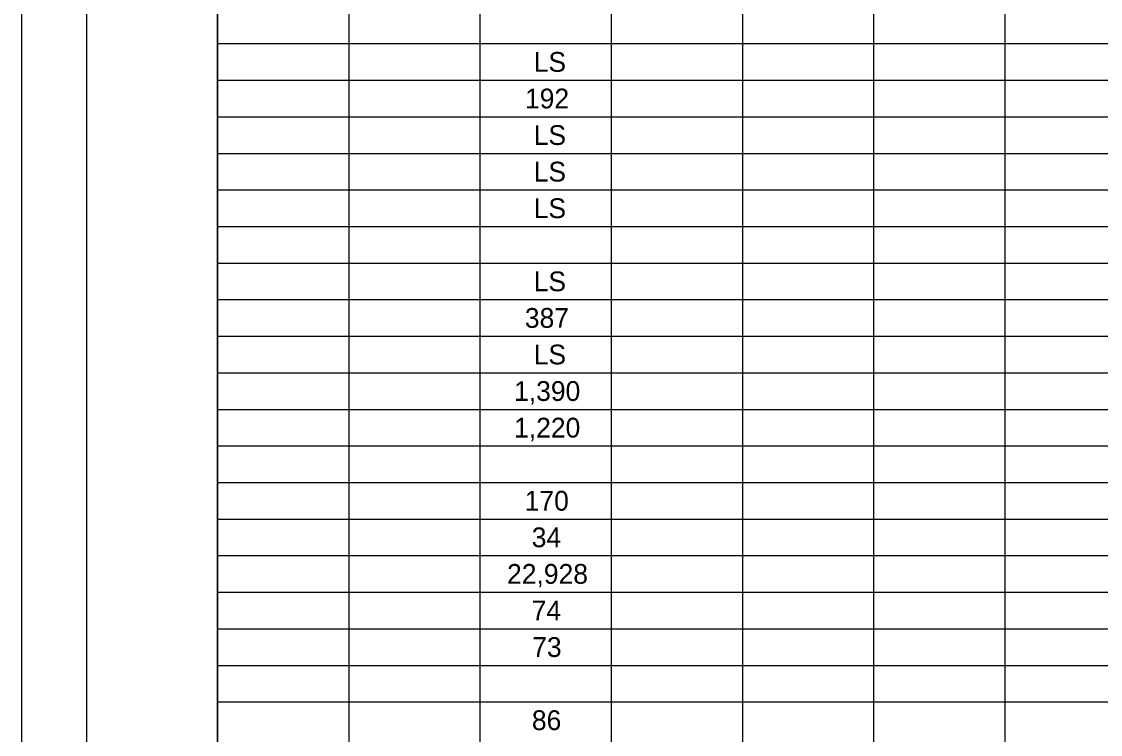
# Model space of a CAD drawing. Extents: x 0 to 34, y 0 to 22.
# Drawn here: x 0 to 8.26, y 10.89 to 16.35 of the extents above; entities that cross this region are included whole.
import ezdxf

# ---------------------------------------------------------------- set-up
doc = ezdxf.new("R2010")
doc.units = 0
for name, color, linetype in [('SH_Border', 7, 'Continuous'), ('SH_Cut_Line', 7, 'Continuous'), ('SH_Text', 7, 'Continuous')]:
    doc.layers.add(name, color=color, linetype=linetype)

msp = doc.modelspace()

# ---------------------------------------------------------------- linework, layer by layer
at = {"layer": 'SH_Border'}
for points in [[(0.5, 21.5), (1.5, 21.5), (1.5, 0.5), (0.5, 0.5)], [(1.5, 21.5), (33.5, 21.5), (33.5, 0.5), (1.5, 0.5)]]:
    msp.add_lwpolyline(points, close=True, dxfattribs=at)
at = {"layer": 'SH_Cut_Line'}
msp.add_lwpolyline([(0, 0), (34, 0), (34, 22), (0, 22)], close=True, dxfattribs=at)
at = {"layer": 'SH_Text'}
for p, q in [((1.5, 21.5), (1.5, 0.5)), ((2.5046, 20.94), (2.5046, 0.5)), ((3.5092, 20.94), (3.5092, 0.5)), ((4.5138, 20.94), (4.5138, 0.5)), ((5.5184, 20.94), (5.5184, 0.5)), ((6.5229, 20.94), (6.5229, 0.5)), ((7.5275, 20.94), (7.5275, 0.5)), ((1.5, 16.18), (32, 16.18)), ((1.5, 15.9), (32, 15.9)), ((1.5, 15.62), (32, 15.62)), ((1.5, 15.34), (32, 15.34)), ((1.5, 15.06), (32, 15.06)), ((1.5, 14.78), (32, 14.78)), ((1.5, 14.5), (32, 14.5)), ((1.5, 14.22), (32, 14.22)), ((1.5, 13.94), (32, 13.94)), ((1.5, 13.66), (32, 13.66)), ((1.5, 13.38), (32, 13.38)), ((1.5, 13.1), (32, 13.1)), ((1.5, 12.82), (32, 12.82)), ((1.5, 12.54), (32, 12.54)), ((1.5, 12.26), (32, 12.26)), ((1.5, 11.98), (32, 11.98)), ((1.5, 11.7), (32, 11.7)), ((1.5, 11.42), (32, 11.42)), ((1.5, 11.14), (32, 11.14))]:
    msp.add_line(p, q, dxfattribs=at)

# ---------------------------------------------------------------- texts
for s, p in [('LS', (3.9209, 15.9642)), ('192', (3.8542, 15.6842)), ('LS', (3.9209, 15.4042)), ('LS', (3.9209, 15.1242)), ('LS', (3.9209, 14.8442)), ('LS', (3.9209, 14.2842)), ('387', (3.8532, 14.0042)), ('LS', (3.9209, 13.7242)), ('1,390', (3.7707, 13.4442)), ('1,220', (3.7707, 13.1642)), ('170', (3.8519, 12.6042)), ('34', (3.9057, 12.3242)), ('22,928', (3.717, 12.0442)), ('74', (3.9057, 11.7642)), ('73', (3.9092, 11.4842)), ('86', (3.9069, 10.9242))]:
    msp.add_text(s, height=0.15153, dxfattribs=at).set_placement(p)

doc.saveas('drawing.dxf')
